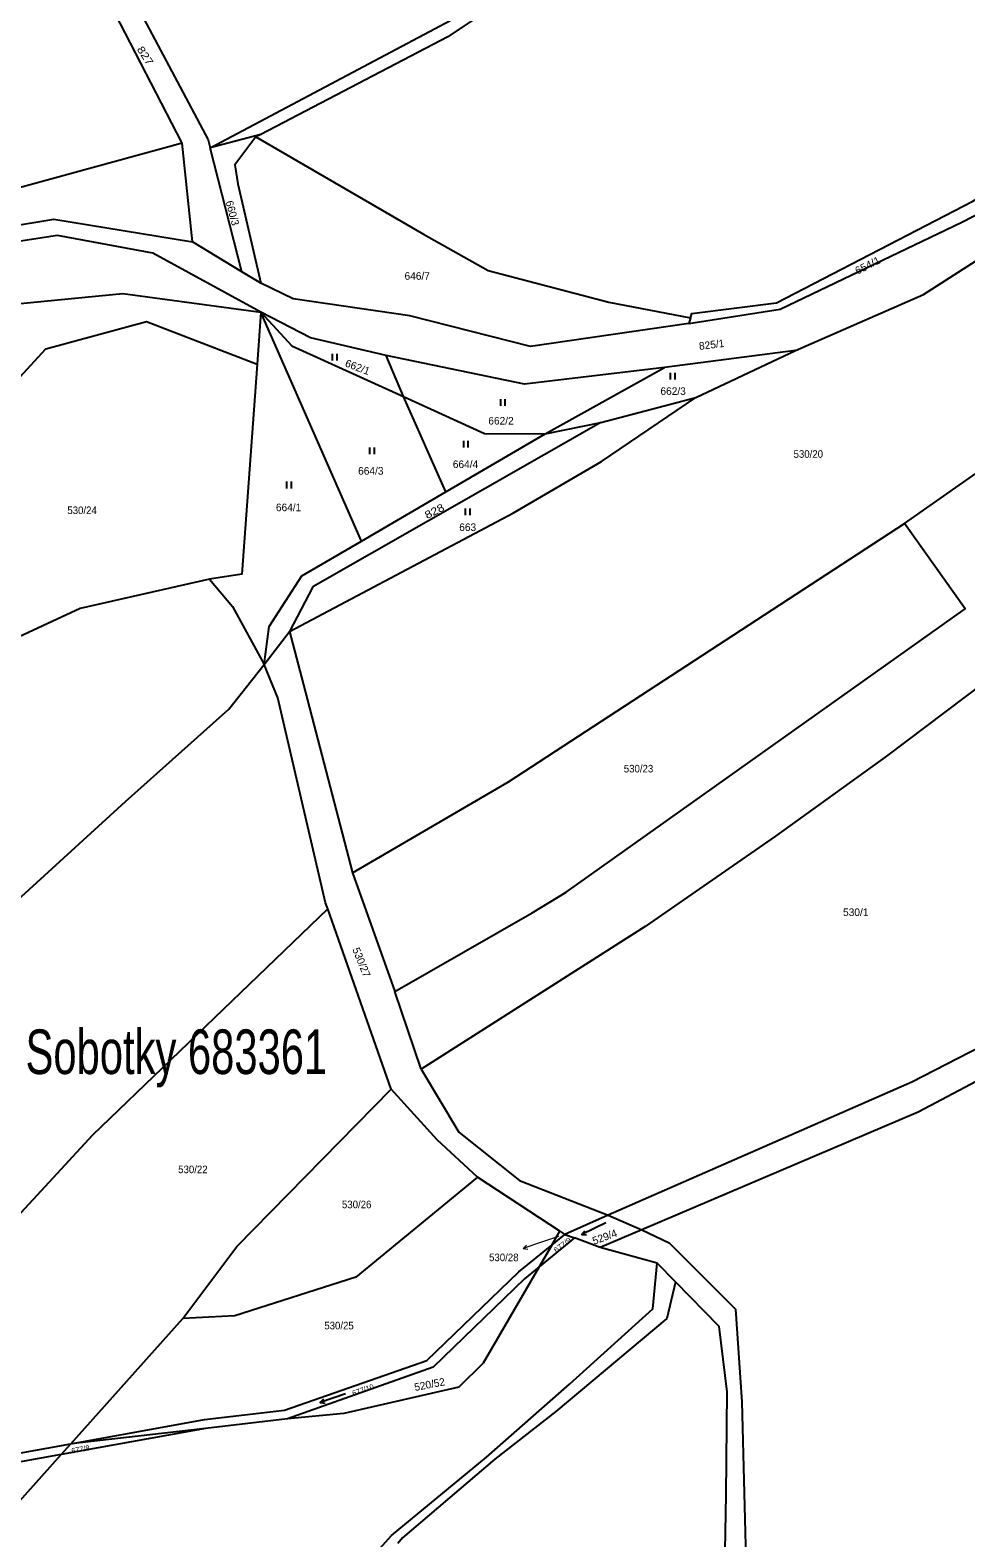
# Model space of a CAD drawing. Extents: x -687135 to -684370, y -1007309 to -1005782.
# Drawn here: x -685609.3 to -685399.4, y -1006924.3 to -1006586 of the extents above; entities that cross this region are included whole.
import ezdxf
from ezdxf.enums import TextEntityAlignment as Align

# ---------------------------------------------------------------- set-up
doc = ezdxf.new("R2010")
doc.units = 0
doc.header["$LTSCALE"] = 0.68
for name, color, linetype, lineweight in [('1', 7, 'Continuous', 25), ('3', 7, 'Continuous', 25), ('7', 7, 'Continuous', 13)]:
    doc.layers.add(name, color=color, linetype=linetype, lineweight=lineweight)
doc.layers.add('2', color=7, linetype='Continuous')

msp = doc.modelspace()

# ---------------------------------------------------------------- linework, layer by layer
at = {"layer": '1'}
for p, q in [((-685557.55, -1006609.41), (-685568.88, -1006612.44)), ((-685557.55, -1006609.41), (-685558.66, -1006609.99)), ((-685561.76, -1006640.24), (-685568.88, -1006612.44)), ((-685461.13, -1006650.6), (-685461.51, -1006651.87)), ((-685525.49, -1006668.26), (-685529.43, -1006659.01)), ((-685493.75, -1006676.61), (-685466.97, -1006661.7)), ((-685493.75, -1006676.61), (-685481.29, -1006674.05)), ((-685516.05, -1006689.59), (-685493.75, -1006676.61)), ((-685556.79, -1006728.34), (-685551.1, -1006720.92)), ((-685537, -1006775.13), (-685527.47, -1006801.74)), ((-685521.55, -1006819.13), (-685527.47, -1006801.74)), ((-685479.62, -1006851.9), (-685472.04, -1006855.16)), ((-685490.49, -1006855.48), (-685489.36, -1006856.21)), ((-685472.04, -1006855.16), (-685481.38, -1006859.19)), ((-685492.29, -1006858.6), (-685495.11, -1006863.46)), ((-685492.29, -1006858.6), (-685489.36, -1006856.21)), ((-685464.49, -1006866.84), (-685468.63, -1006862.64)), ((-685569.93, -1006899.75), (-685600.16, -1006903.18)), ((-685602.32, -1006905.6), (-685600.16, -1006903.18))]:
    msp.add_line(p, q, dxfattribs=at)
for points in [[(-685401.24, -1006511.39), (-685409.65, -1006511.84), (-685411.62, -1006511.95), (-685422.41, -1006512.53), (-685438.3, -1006519.76), (-685467.67, -1006551.95), (-685482.1, -1006565.02), (-685515.6, -1006587.5), (-685557.55, -1006609.41)], [(-685568.88, -1006612.44), (-685512.33, -1006582.44), (-685482.34, -1006561.69), (-685469.36, -1006548.75), (-685439.84, -1006516.97)], [(-685599.53, -1006553.75), (-685569.3, -1006610.61), (-685568.88, -1006612.44)], [(-685575.17, -1006611.42), (-685598.35, -1006566.45), (-685603.34, -1006559.03), (-685608.88, -1006566.69)], [(-685461.51, -1006651.87), (-685441.02, -1006648.66), (-685400.31, -1006629.14), (-685382.75, -1006620.03), (-685367.14, -1006610.32), (-685336.98, -1006592.43)], [(-685461.13, -1006650.6), (-685460.84, -1006649.6), (-685441.89, -1006647.2), (-685397.85, -1006624.39), (-685361.58, -1006602.4)], [(-685437.58, -1006657.94), (-685408.86, -1006645.35), (-685350.72, -1006607.99)], [(-685575.17, -1006611.42), (-685614.74, -1006622.25), (-685656.12, -1006626.09), (-685656.29, -1006638.32)], [(-685656.29, -1006638.32), (-685644.27, -1006635.08), (-685603.94, -1006628.44), (-685572.86, -1006633.51), (-685575.17, -1006611.42)], [(-685558.66, -1006609.99), (-685563.32, -1006616.22), (-685562.7, -1006620.52), (-685557.52, -1006642.81)], [(-685558.66, -1006609.99), (-685521.07, -1006631.77), (-685506.54, -1006639.92), (-685479.46, -1006647.06), (-685461.13, -1006650.6)], [(-685557.54, -1006649.32), (-685581.72, -1006636.09), (-685603.1, -1006632.14), (-685613.39, -1006633.71)], [(-685461.51, -1006651.87), (-685497.07, -1006657.03), (-685524.07, -1006650.14), (-685550.29, -1006646.29), (-685557.52, -1006642.81), (-685561.76, -1006640.24), (-685572.86, -1006633.51)], [(-685413.15, -1006696.73), (-685384.89, -1006676.88), (-685341.29, -1006645.97), (-685335.02, -1006641.79)], [(-685671.21, -1006744.5), (-685646.88, -1006673.94), (-685612.23, -1006647.46), (-685588.5, -1006645.15), (-685557.54, -1006649.32)], [(-685534.93, -1006700.67), (-685557.54, -1006649.32), (-685558.38, -1006660.99)], [(-685529.43, -1006659.01), (-685546.4, -1006655.1), (-685557.54, -1006649.32)], [(-685557.54, -1006649.32), (-685550.58, -1006656.87), (-685525.49, -1006668.26)], [(-685671.21, -1006744.5), (-685623.21, -1006676.54), (-685605.72, -1006657.51), (-685583.18, -1006651.43), (-685558.38, -1006660.99)], [(-685466.97, -1006661.7), (-685498.42, -1006665.46), (-685529.43, -1006659.01)], [(-685481.29, -1006674.05), (-685459.95, -1006668.42), (-685437.58, -1006657.94), (-685466.97, -1006661.7)], [(-685558.38, -1006660.99), (-685561.77, -1006708.1), (-685569.03, -1006709.19)], [(-685551.1, -1006720.92), (-685500.83, -1006694.29), (-685481.13, -1006682.84), (-685459.95, -1006668.42)], [(-685534.93, -1006700.67), (-685516.05, -1006689.59), (-685525.49, -1006668.26)], [(-685525.49, -1006668.26), (-685507.37, -1006676.54), (-685493.75, -1006676.61)], [(-685481.29, -1006674.05), (-685545.86, -1006710.91), (-685551.1, -1006720.92)], [(-685313.7, -1006675.14), (-685381.87, -1006722.26), (-685417.2, -1006748.9), (-685442.1, -1006766.87), (-685471.35, -1006787.14), (-685521.55, -1006819.13)], [(-685537, -1006775.13), (-685501.96, -1006754.68), (-685413.15, -1006696.73)], [(-685527.47, -1006801.74), (-685496.63, -1006784.04), (-685489.01, -1006779.41), (-685399.52, -1006715.86), (-685413.15, -1006696.73)], [(-685556.79, -1006728.34), (-685555.63, -1006719.82), (-685548.33, -1006708.45), (-685534.93, -1006700.67)], [(-685569.03, -1006709.19), (-685598.05, -1006715.78), (-685631.8, -1006731.45)], [(-685569.03, -1006709.19), (-685563.91, -1006715.31), (-685556.79, -1006728.34)], [(-685272.78, -1006712.27), (-685326.02, -1006757.61), (-685369.95, -1006800.7), (-685411.54, -1006822.08), (-685479.62, -1006851.9)], [(-685270.27, -1006715.95), (-685321.6, -1006762.38), (-685365.8, -1006805.42), (-685410.08, -1006828.78), (-685472.04, -1006855.16)], [(-685551.1, -1006720.92), (-685548.42, -1006731.2), (-685537, -1006775.13)], [(-685691.91, -1006852.16), (-685690.99, -1006851.65), (-685665.96, -1006829.87), (-685627.75, -1006795.4), (-685587.91, -1006759.11), (-685564.69, -1006738.38), (-685556.79, -1006728.34)], [(-685542.53, -1006783.15), (-685543.01, -1006781.79), (-685553.71, -1006735.82), (-685556.79, -1006728.34)], [(-685658.94, -1006900.62), (-685630.94, -1006872.36), (-685628.68, -1006870.1), (-685627.38, -1006868.69), (-685595.17, -1006833.9), (-685542.53, -1006783.15)], [(-685575.05, -1006875.09), (-685562.92, -1006858.93), (-685528.26, -1006823.65), (-685542.53, -1006783.15)], [(-685521.55, -1006819.13), (-685513.11, -1006833.3), (-685499.54, -1006844.11), (-685479.62, -1006851.9)], [(-685508.94, -1006843.34), (-685517.94, -1006834.98), (-685528.26, -1006823.65)], [(-685508.94, -1006843.34), (-685536.2, -1006865.84), (-685563.35, -1006874.45), (-685575.05, -1006875.09)], [(-685492.29, -1006858.6), (-685490.49, -1006855.48), (-685508.94, -1006843.34)], [(-685479.62, -1006851.9), (-685489.36, -1006856.21), (-685487.19, -1006857.02)], [(-685472.04, -1006855.16), (-685465.95, -1006858.14), (-685451.07, -1006873.02), (-685449.67, -1006893.75), (-685448.06, -1006955.29), (-685448.01, -1006975.35), (-685454.75, -1007052.16), (-685344.34, -1007065.04)], [(-685600.16, -1006903.18), (-685570.16, -1006897.76), (-685552.21, -1006895.67), (-685520.29, -1006884.53), (-685499.67, -1006864.6), (-685492.29, -1006858.6)], [(-685468.63, -1006862.64), (-685481.38, -1006859.19), (-685487.19, -1006857.02), (-685495.11, -1006863.46)], [(-685600.31, -1007021.4), (-685571.01, -1006972.89), (-685550.99, -1006949.11), (-685528.25, -1006923.76), (-685506.88, -1006906.22), (-685488.26, -1006889.79), (-685469.63, -1006872.88), (-685468.63, -1006862.64)], [(-685495.11, -1006863.46), (-685507.65, -1006885.13), (-685513.09, -1006890.46), (-685538.88, -1006896.41), (-685551.55, -1006897.56), (-685569.93, -1006899.75), (-685602.32, -1006905.6)], [(-685495.11, -1006863.46), (-685498.41, -1006866.15), (-685518.9, -1006885.97), (-685551.55, -1006897.56)], [(-685464.49, -1006866.84), (-685466.45, -1006875.07), (-685491.38, -1006895.96), (-685505.02, -1006906.65), (-685525.78, -1006924.31), (-685526.83, -1006925.6)], [(-685487.65, -1007102.28), (-685486.22, -1007099.21), (-685477.56, -1007085.22), (-685464.8, -1007050), (-685461.61, -1007028.25), (-685454.62, -1006977.75), (-685453.91, -1006956.43), (-685453.17, -1006914.64), (-685452.94, -1006891.57), (-685454.7, -1006876.89), (-685464.49, -1006866.84)], [(-685658.94, -1006900.62), (-685616.35, -1006906.11), (-685600.16, -1006903.18), (-685575.05, -1006875.09)], [(-685602.32, -1006905.6), (-685615.99, -1006908.08), (-685662.46, -1006904.3)], [(-685662.46, -1006904.3), (-685636.48, -1006922.07), (-685616.01, -1006920.93), (-685602.32, -1006905.6)]]:
    msp.add_lwpolyline(points, dxfattribs=at)
at = {"layer": '3'}
for p, q in [((-685541.421, -1006660.13), (-685541.421, -1006658.63)), ((-685540.42, -1006660.13), (-685540.42, -1006658.63)), ((-685465.611, -1006664.42), (-685465.611, -1006662.92)), ((-685464.61, -1006664.42), (-685464.61, -1006662.92)), ((-685503.711, -1006670.35), (-685503.711, -1006668.85)), ((-685502.71, -1006670.35), (-685502.71, -1006668.85)), ((-685533.041, -1006681.19), (-685533.041, -1006679.69)), ((-685532.04, -1006681.19), (-685532.04, -1006679.69)), ((-685511.991, -1006679.7), (-685511.991, -1006678.2)), ((-685510.99, -1006679.7), (-685510.99, -1006678.2)), ((-685551.671, -1006688.83), (-685551.671, -1006687.33)), ((-685550.67, -1006688.83), (-685550.67, -1006687.33)), ((-685511.601, -1006694.83), (-685511.601, -1006693.33)), ((-685510.6, -1006694.83), (-685510.6, -1006693.33)), ((-685485.546, -1006856.265), (-685484.887, -1006855.386)), ((-685544.186, -1006893.904), (-685543.425, -1006893.112))]:
    msp.add_line(p, q, dxfattribs=at)
for points in [[(-685480.153, -1006853.635), (-685485.546, -1006856.265), (-685484.447, -1006856.287)], [(-685538.512, -1006891.951), (-685544.186, -1006893.904), (-685543.098, -1006894.06)]]:
    msp.add_lwpolyline(points, dxfattribs=at)
at = {"layer": '7'}
msp.add_line((-685498.717, -1006859.397), (-685497.608, -1006859.544), dxfattribs=at)
msp.add_lwpolyline([(-685490.79, -1006856.69), (-685495.88, -1006858.42), (-685498.717, -1006859.397), (-685497.934, -1006858.598)], dxfattribs=at)

# ---------------------------------------------------------------- texts
at = {"layer": '2'}
for s, height, rotation, width, p in [('827', 1.7, 303, 1.2, (-685585.412, -1006590.322)), ('654/1', 1.7, 27, 1.05, (-685423.704, -1006640.917)), ('828', 1.7, 27, 1.2, (-685520.224, -1006695.737)), ('677/9', 1.19, 37, 1.1, (-685491.271, -1006860.375))]:
    msp.add_text(s, height=height, rotation=rotation, dxfattribs=dict(at, width=width)).set_placement(p)
for s, height, rotation, p in [('660/3', 1.7, 285, (-685565.441, -1006624.539)), ('825/1', 1.7, 7, (-685459.136, -1006657.783)), ('662/1', 1.7, 339, (-685538.784, -1006661.413)), ('530/27', 1.7, 292, (-685537.038, -1006792.268)), ('529/4', 1.7, 20, (-685482.789, -1006858.558)), ('520/52', 1.7, 11, (-685522.917, -1006891.364)), ('677/10', 1.19, 19, (-685536.796, -1006892.482)), ('677/8', 1.19, 10, (-685599.896, -1006905.375))]:
    msp.add_text(s, height=height, rotation=rotation, dxfattribs=at).set_placement(p)
for s, p in [('646/7', (-685525.29, -1006642.039)), ('662/3', (-685467.89, -1006667.87)), ('662/2', (-685506.5, -1006674.52)), ('664/4', (-685514.46, -1006684.27)), ('664/3', (-685535.7, -1006685.76)), ('664/1', (-685554.14, -1006693.96)), ('663', (-685513.02, -1006698.4)), ('530/1', (-685426.93, -1006784.78))]:
    msp.add_text(s, height=1.7, dxfattribs=at).set_placement(p)
at = {"layer": '2', "width": 0.95}
for s, p in [('530/20', (-685438.03, -1006681.98)), ('530/24', (-685600.92, -1006694.6)), ('530/23', (-685476.11, -1006752.57)), ('530/22', (-685576.06, -1006842.48)), ('530/26', (-685539.33, -1006850.35)), ('530/25', (-685543.29, -1006877.52))]:
    msp.add_text(s, height=1.7, dxfattribs=at).set_placement(p)
msp.add_text('530/28', height=1.7, dxfattribs=at).set_placement((-685499.72, -1006862.223), align=Align.RIGHT)
at = {"layer": '7', "width": 0.7}
msp.add_text('Vesec u Sobotky 683361', height=10, dxfattribs=at).set_placement((-685594.68, -1006820.237), align=Align.CENTER)

doc.saveas('drawing.dxf')
